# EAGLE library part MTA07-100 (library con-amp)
AMP connector
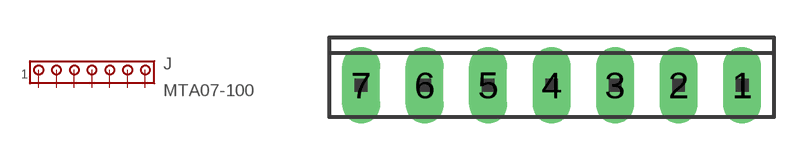
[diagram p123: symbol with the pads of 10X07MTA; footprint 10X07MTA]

Designator prefix J

## MTA07-100 (OC_FARNELL: unknown; OC_NEWARK: unknown)  [10X07MTA]
1  1  pas
2  2  pas
3  3  pas
4  4  pas
5  5  pas
6  6  pas
7  7  pas

## Footprint 10X07MTA (pad centres in mm)
AMP MTA connector Source: http://ecommas.tycoelectronics.com .. ENG_CD_640456_W.pdf
drill 1.016 long: 1 7.62,0; 2 5.08,0; 3 2.54,0; 4 0,0; 5 -2.54,0; 6 -5.08,0; 7 -7.62,0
